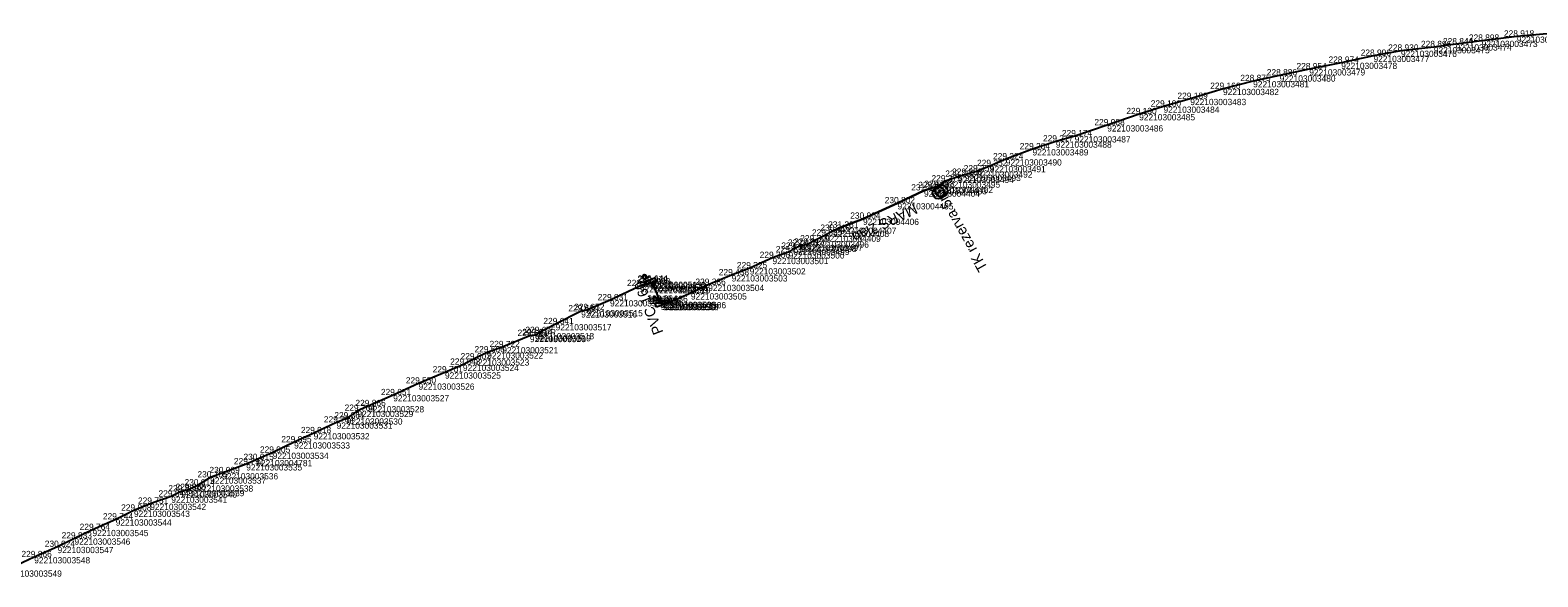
# Model space of a CAD drawing. Extents: x -771047 to -756200, y -1053876 to -1046520.
# Drawn here: x -770297.8 to -770008.9, y -1050222.5 to -1050117.8 of the extents above; entities that cross this region are included whole.
import ezdxf

# ---------------------------------------------------------------- set-up
doc = ezdxf.new("R2010")
doc.units = 0
for name, color, linetype in [('Vrstva 32', 7, 'Continuous'), ('Vrstva 33', 7, 'Continuous'), ('Vrstva 60', 7, 'Continuous'), ('Vrstva 61', 7, 'Continuous')]:
    doc.layers.add(name, color=color, linetype=linetype)

msp = doc.modelspace()

# ---------------------------------------------------------------- linework, layer by layer
at = {"layer": 'Vrstva 32'}
for points in [[(-770006.4, -1050118.41), (-770012.92, -1050119.01), (-770019.65, -1050119.81), (-770024.62, -1050120.5), (-770028.82, -1050121.03), (-770035.11, -1050121.72), (-770040.38, -1050122.7), (-770046.55, -1050124.03), (-770052.68, -1050125.27), (-770058.36, -1050126.45), (-770063.44, -1050127.54), (-770069.21, -1050129.03), (-770075.48, -1050130.95), (-770080.61, -1050132.42), (-770085.28, -1050133.87), (-770091.39, -1050136), (-770097.63, -1050138.1), (-770101.25, -1050139.11), (-770105.71, -1050140.59), (-770110.82, -1050142.52), (-770113.89, -1050143.81), (-770116.43, -1050144.83), (-770118.67, -1050145.49), (-770119.98, -1050145.87), (-770122.62, -1050146.76), (-770124, -1050147.81), (-770125.15, -1050148.04), (-770126.5, -1050148.49), (-770131.58, -1050150.93), (-770138.18, -1050153.9), (-770142.51, -1050155.61), (-770143.91, -1050156.22), (-770145.5, -1050157.13), (-770147.77, -1050158.25), (-770148.95, -1050158.89), (-770150.13, -1050159.07), (-770151.49, -1050159.65), (-770152.44, -1050160.33), (-770155.53, -1050161.41), (-770159.89, -1050163.39), (-770163.36, -1050164.73), (-770167.85, -1050166.57), (-770171.16, -1050168.19), (-770175.13, -1050169.86), (-770176.29, -1050170.25)], [(-770178.93, -1050166.17), (-770180.95, -1050166.81), (-770186.66, -1050169.51), (-770191.08, -1050171.4), (-770192.19, -1050171.63), (-770197.08, -1050174.1), (-770200.42, -1050175.8), (-770201.02, -1050176.2), (-770202.01, -1050176.35), (-770207.3, -1050178.5), (-770210.18, -1050179.5), (-770212.84, -1050180.83), (-770214.84, -1050181.87), (-770218.28, -1050183.34), (-770223.34, -1050185.46), (-770228.2, -1050187.7), (-770232.99, -1050189.8), (-770235.06, -1050190.7), (-770237.12, -1050192.15), (-770239.04, -1050192.93), (-770243.44, -1050194.98), (-770247.19, -1050196.73), (-770251.28, -1050198.71), (-770254.43, -1050200.12), (-770256.36, -1050200.93), (-770260.96, -1050202.64), (-770263.26, -1050203.46), (-770265.73, -1050204.99), (-770267.43, -1050205.86), (-770268.84, -1050206.15), (-770270.72, -1050207.12), (-770274.75, -1050208.5), (-770277.87, -1050209.82), (-770281.37, -1050211.5), (-770285.82, -1050213.51), (-770289.28, -1050215.15), (-770292.51, -1050216.76), (-770296.98, -1050218.73), (-770302.4, -1050221.28)], [(-770176.29, -1050170.25), (-770176.65, -1050170.22), (-770177.07, -1050169.78), (-770178.13, -1050167), (-770178.47, -1050166.46), (-770178.93, -1050166.17)]]:
    msp.add_lwpolyline(points, dxfattribs=at)
for centre in [(-770123.69, -1050148.94), (-770123.14, -1050148.6)]:
    msp.add_circle(centre, 1.17, dxfattribs=at)
at = {"layer": 'Vrstva 33'}
for points in [[(-770143.91, -1050156.22), (-770142.51, -1050155.61), (-770138.18, -1050153.9), (-770131.58, -1050150.93), (-770126.5, -1050148.49), (-770125.15, -1050148.04)], [(-770180.37, -1050164.99), (-770180.37, -1050164.83), (-770180.22, -1050164.65), (-770180.12, -1050164.61), (-770179.89, -1050164.64), (-770179.79, -1050164.77)], [(-770180.18, -1050165.48), (-770180.37, -1050164.99)], [(-770179.01, -1050165.03), (-770180.18, -1050165.48)], [(-770179.79, -1050164.77), (-770179.6, -1050165.26)], [(-770176.29, -1050170.25), (-770176.65, -1050170.22), (-770177.07, -1050169.78), (-770178.13, -1050167), (-770178.47, -1050166.46), (-770178.93, -1050166.17)], [(-770178.41, -1050169.2), (-770178.42, -1050169.03), (-770178.27, -1050168.85), (-770178.17, -1050168.82), (-770177.93, -1050168.84), (-770177.83, -1050168.98)], [(-770178.23, -1050169.68), (-770178.41, -1050169.2)], [(-770177.05, -1050169.24), (-770178.23, -1050169.68)], [(-770177.83, -1050168.98), (-770177.65, -1050169.46)]]:
    msp.add_lwpolyline(points, dxfattribs=at)
for points in [[(-770179.72, -1050166.66), (-770179.99, -1050165.97), (-770178.11, -1050165.25), (-770177.84, -1050165.95)], [(-770177.77, -1050170.87), (-770178.04, -1050170.17), (-770176.15, -1050169.45), (-770175.89, -1050170.15)]]:
    msp.add_lwpolyline(points, close=True, dxfattribs=at)
at = {"layer": 'Vrstva 60'}
for p, q in [((-770012.92, -1050119.01), (-770012.92, -1050119.01)), ((-770035.11, -1050121.72), (-770035.11, -1050121.72)), ((-770028.82, -1050121.03), (-770028.82, -1050121.03)), ((-770024.62, -1050120.5), (-770024.62, -1050120.5)), ((-770019.65, -1050119.81), (-770019.65, -1050119.81)), ((-770052.68, -1050125.27), (-770052.68, -1050125.27)), ((-770046.55, -1050124.03), (-770046.55, -1050124.03)), ((-770040.38, -1050122.7), (-770040.38, -1050122.7)), ((-770063.44, -1050127.54), (-770063.44, -1050127.54)), ((-770058.36, -1050126.45), (-770058.36, -1050126.45)), ((-770075.48, -1050130.95), (-770075.48, -1050130.95)), ((-770069.21, -1050129.03), (-770069.21, -1050129.03)), ((-770085.28, -1050133.87), (-770085.28, -1050133.87)), ((-770080.61, -1050132.42), (-770080.61, -1050132.42)), ((-770091.39, -1050136), (-770091.39, -1050136)), ((-770101.25, -1050139.11), (-770101.25, -1050139.11)), ((-770097.63, -1050138.1), (-770097.63, -1050138.1)), ((-770110.82, -1050142.52), (-770110.82, -1050142.52)), ((-770105.71, -1050140.59), (-770105.71, -1050140.59)), ((-770118.67, -1050145.49), (-770118.67, -1050145.49)), ((-770116.43, -1050144.83), (-770116.43, -1050144.83)), ((-770113.89, -1050143.81), (-770113.89, -1050143.81)), ((-770126.5, -1050148.49), (-770126.5, -1050148.49)), ((-770125.15, -1050148.04), (-770125.15, -1050148.04)), ((-770124, -1050147.81), (-770124, -1050147.81)), ((-770122.62, -1050146.76), (-770122.62, -1050146.76)), ((-770119.98, -1050145.87), (-770119.98, -1050145.87)), ((-770131.58, -1050150.93), (-770131.58, -1050150.93)), ((-770138.18, -1050153.9), (-770138.18, -1050153.9)), ((-770145.5, -1050157.13), (-770145.5, -1050157.13)), ((-770143.91, -1050156.22), (-770143.91, -1050156.22)), ((-770142.51, -1050155.61), (-770142.51, -1050155.61)), ((-770151.49, -1050159.65), (-770151.49, -1050159.65)), ((-770150.13, -1050159.07), (-770150.13, -1050159.07)), ((-770148.95, -1050158.89), (-770148.95, -1050158.89)), ((-770147.77, -1050158.25), (-770147.77, -1050158.25)), ((-770155.53, -1050161.41), (-770155.53, -1050161.41)), ((-770152.44, -1050160.33), (-770152.44, -1050160.33)), ((-770178.92, -1050165.96), (-770178.92, -1050165.96)), ((-770163.36, -1050164.73), (-770163.36, -1050164.73)), ((-770159.89, -1050163.39), (-770159.89, -1050163.39)), ((-770180.95, -1050166.81), (-770180.95, -1050166.81)), ((-770178.93, -1050166.17), (-770178.93, -1050166.17)), ((-770178.47, -1050166.46), (-770178.47, -1050166.46)), ((-770178.13, -1050167), (-770178.13, -1050167)), ((-770171.16, -1050168.19), (-770171.16, -1050168.19)), ((-770167.85, -1050166.57), (-770167.85, -1050166.57)), ((-770192.19, -1050171.63), (-770192.19, -1050171.63)), ((-770191.08, -1050171.4), (-770191.08, -1050171.4)), ((-770186.66, -1050169.51), (-770186.66, -1050169.51)), ((-770177.07, -1050169.78), (-770177.07, -1050169.78)), ((-770176.96, -1050170.16), (-770176.96, -1050170.16)), ((-770176.65, -1050170.22), (-770176.65, -1050170.22)), ((-770176.29, -1050170.25), (-770176.29, -1050170.25)), ((-770175.13, -1050169.86), (-770175.13, -1050169.86)), ((-770197.08, -1050174.1), (-770197.08, -1050174.1)), ((-770202.01, -1050176.35), (-770202.01, -1050176.35)), ((-770201.02, -1050176.2), (-770201.02, -1050176.2)), ((-770200.42, -1050175.8), (-770200.42, -1050175.8)), ((-770210.18, -1050179.5), (-770210.18, -1050179.5)), ((-770207.3, -1050178.5), (-770207.3, -1050178.5)), ((-770214.84, -1050181.87), (-770214.84, -1050181.87)), ((-770212.84, -1050180.83), (-770212.84, -1050180.83)), ((-770223.34, -1050185.46), (-770223.34, -1050185.46)), ((-770218.28, -1050183.34), (-770218.28, -1050183.34)), ((-770228.2, -1050187.7), (-770228.2, -1050187.7)), ((-770235.06, -1050190.7), (-770235.06, -1050190.7)), ((-770232.99, -1050189.8), (-770232.99, -1050189.8)), ((-770239.04, -1050192.93), (-770239.04, -1050192.93)), ((-770237.12, -1050192.15), (-770237.12, -1050192.15)), ((-770247.19, -1050196.73), (-770247.19, -1050196.73)), ((-770243.44, -1050194.98), (-770243.44, -1050194.98)), ((-770254.43, -1050200.12), (-770254.43, -1050200.12)), ((-770251.28, -1050198.71), (-770251.28, -1050198.71)), ((-770263.26, -1050203.46), (-770263.26, -1050203.46)), ((-770260.96, -1050202.64), (-770260.96, -1050202.64)), ((-770256.36, -1050200.93), (-770256.36, -1050200.93)), ((-770268.84, -1050206.15), (-770268.84, -1050206.15)), ((-770267.43, -1050205.86), (-770267.43, -1050205.86)), ((-770265.73, -1050204.99), (-770265.73, -1050204.99)), ((-770274.75, -1050208.5), (-770274.75, -1050208.5)), ((-770270.72, -1050207.12), (-770270.72, -1050207.12)), ((-770281.37, -1050211.5), (-770281.37, -1050211.5)), ((-770277.87, -1050209.82), (-770277.87, -1050209.82)), ((-770285.82, -1050213.51), (-770285.82, -1050213.51)), ((-770292.51, -1050216.76), (-770292.51, -1050216.76)), ((-770289.28, -1050215.15), (-770289.28, -1050215.15)), ((-770296.98, -1050218.73), (-770296.98, -1050218.73))]:
    msp.add_line(p, q, dxfattribs=at)

# ---------------------------------------------------------------- texts
at = {"layer": 'Vrstva 32'}
msp.add_text('TK rezerva 5m', height=2, rotation=119.2441, dxfattribs=at).set_placement((-770114.24, -1050163.36))
at = {"layer": 'Vrstva 33'}
for s, rotation, p in [('MARS žlab', 205.6293, (-770128.4, -1050150.95)), ('PVC 160', 110.8407, (-770176.42, -1050175.65))]:
    msp.add_text(s, height=2, rotation=rotation, dxfattribs=at).set_placement(p)
at = {"layer": 'Vrstva 60'}
for s, p in [('922103003472', (-770012.92, -1050120.21)), ('922103003476', (-770035.11, -1050122.92)), ('922103003475', (-770028.82, -1050122.23)), ('922103003474', (-770024.62, -1050121.7)), ('922103003473', (-770019.65, -1050121.02)), ('922103003479', (-770052.68, -1050126.47)), ('922103003478', (-770046.55, -1050125.23)), ('922103003477', (-770040.38, -1050123.9)), ('922103003481', (-770063.44, -1050128.74)), ('922103003480', (-770058.36, -1050127.65)), ('922103003483', (-770075.48, -1050132.15)), ('922103003482', (-770069.21, -1050130.23)), ('922103003485', (-770085.28, -1050135.07)), ('922103003484', (-770080.61, -1050133.62)), ('922103003486', (-770091.39, -1050137.2)), ('922103003488', (-770101.25, -1050140.31)), ('922103003487', (-770097.63, -1050139.3)), ('922103003490', (-770110.82, -1050143.72)), ('922103003489', (-770105.71, -1050141.79)), ('922103003493', (-770118.67, -1050146.69)), ('922103003492', (-770116.43, -1050146.03)), ('922103003491', (-770113.89, -1050145.01)), ('922103004404', (-770126.5, -1050149.69)), ('922103004403', (-770125.15, -1050149.24)), ('922103004402', (-770124, -1050149.01)), ('922103003495', (-770122.62, -1050147.96)), ('922103003494', (-770119.98, -1050147.07)), ('922103004405', (-770131.58, -1050152.13)), ('922103004406', (-770138.18, -1050155.1)), ('922103004409', (-770145.5, -1050158.33)), ('922103004408', (-770143.91, -1050157.42)), ('922103004407', (-770142.51, -1050156.81)), ('922103003499', (-770151.49, -1050160.85)), ('922103003498', (-770150.13, -1050160.27)), ('922103003497', (-770148.95, -1050160.09)), ('922103003496', (-770147.77, -1050159.45)), ('922103003501', (-770155.53, -1050162.61)), ('922103003500', (-770152.44, -1050161.53)), ('922103005131', (-770178.92, -1050167.16)), ('922103003503', (-770163.36, -1050165.93)), ('922103003502', (-770159.89, -1050164.59)), ('922103003513', (-770180.95, -1050168.02)), ('922103003512', (-770178.93, -1050167.37)), ('922103003511', (-770178.47, -1050167.66)), ('922103003510', (-770178.13, -1050168.2)), ('922103003505', (-770171.16, -1050169.39)), ('922103003504', (-770167.85, -1050167.77)), ('922103003516', (-770192.19, -1050172.83)), ('922103003515', (-770191.08, -1050172.6)), ('922103003514', (-770186.66, -1050170.71)), ('922103003509', (-770177.07, -1050170.98)), ('922103005130', (-770176.96, -1050171.36)), ('922103003508', (-770176.65, -1050171.42)), ('922103003507', (-770176.29, -1050171.45)), ('922103003506', (-770175.13, -1050171.06)), ('922103003517', (-770197.08, -1050175.3)), ('922103003520', (-770202.01, -1050177.55)), ('922103003519', (-770201.02, -1050177.4)), ('922103003518', (-770200.42, -1050177)), ('922103003522', (-770210.18, -1050180.7)), ('922103003521', (-770207.3, -1050179.7)), ('922103003524', (-770214.84, -1050183.07)), ('922103003523', (-770212.84, -1050182.03)), ('922103003526', (-770223.34, -1050186.66)), ('922103003525', (-770218.28, -1050184.54)), ('922103003527', (-770228.2, -1050188.9)), ('922103003529', (-770235.06, -1050191.9)), ('922103003528', (-770232.99, -1050191)), ('922103003531', (-770239.04, -1050194.13)), ('922103003530', (-770237.12, -1050193.35)), ('922103003533', (-770247.19, -1050197.93)), ('922103003532', (-770243.44, -1050196.18)), ('922103004781', (-770254.43, -1050201.32)), ('922103003534', (-770251.28, -1050199.91)), ('922103003537', (-770263.26, -1050204.66)), ('922103003536', (-770260.96, -1050203.84)), ('922103003535', (-770256.36, -1050202.13)), ('922103003540', (-770268.84, -1050207.35)), ('922103003539', (-770267.43, -1050207.06)), ('922103003538', (-770265.73, -1050206.19)), ('922103003542', (-770274.75, -1050209.7)), ('922103003541', (-770270.72, -1050208.32)), ('922103003544', (-770281.37, -1050212.7)), ('922103003543', (-770277.87, -1050211.02)), ('922103003545', (-770285.82, -1050214.71)), ('922103003547', (-770292.51, -1050217.96)), ('922103003546', (-770289.28, -1050216.35)), ('922103003548', (-770296.98, -1050219.93)), ('922103003549', (-770302.4, -1050222.48))]:
    msp.add_text(s, height=1.2, dxfattribs=at).set_placement(p)
at = {"layer": 'Vrstva 61'}
for s, p in [('228.844', (-770027.07, -1050120.5)), ('228.898', (-770022.1, -1050119.81)), ('228.918', (-770015.38, -1050119.01)), ('228.996', (-770042.83, -1050122.7)), ('228.930', (-770037.56, -1050121.72)), ('228.896', (-770031.28, -1050121.03)), ('228.886', (-770060.82, -1050126.45)), ('228.954', (-770055.13, -1050125.27)), ('228.974', (-770049, -1050124.03)), ('229.166', (-770071.66, -1050129.03)), ('228.875', (-770065.9, -1050127.54)), ('229.100', (-770083.06, -1050132.42)), ('229.189', (-770077.94, -1050130.95)), ('229.130', (-770087.73, -1050133.87)), ('229.174', (-770100.08, -1050138.1)), ('229.088', (-770093.85, -1050136)), ('229.284', (-770108.16, -1050140.59)), ('229.217', (-770103.7, -1050139.11)), ('229.352', (-770116.34, -1050143.81)), ('229.324', (-770113.27, -1050142.52)), ('229.375', (-770125.07, -1050146.76)), ('229.282', (-770122.43, -1050145.87)), ('229.238', (-770121.12, -1050145.49)), ('229.359', (-770118.89, -1050144.83)), ('231.292', (-770128.95, -1050148.49)), ('229.823', (-770127.61, -1050148.04)), ('229.498', (-770126.46, -1050147.81)), ('230.802', (-770134.03, -1050150.93)), ('231.281', (-770144.87, -1050155.61)), ('230.904', (-770140.63, -1050153.9)), ('229.300', (-770150.22, -1050158.25)), ('229.635', (-770147.96, -1050157.13)), ('230.210', (-770146.36, -1050156.22)), ('229.306', (-770157.98, -1050161.41)), ('229.230', (-770154.89, -1050160.33)), ('229.401', (-770153.84, -1050159.65)), ('229.473', (-770152.58, -1050159.07)), ('229.313', (-770151.4, -1050158.89)), ('229.325', (-770162.35, -1050163.39)), ('229.652', (-770183.4, -1050166.81)), ('230.079', (-770181.38, -1050166.17)), ('230.644', (-770181.37, -1050165.96)), ('229.988', (-770180.92, -1050166.46)), ('229.179', (-770180.58, -1050167)), ('229.386', (-770170.3, -1050166.57)), ('229.438', (-770165.82, -1050164.73)), ('229.931', (-770189.02, -1050169.51)), ('229.064', (-770179.52, -1050169.78)), ('229.636', (-770177.58, -1050169.86)), ('229.399', (-770173.62, -1050168.19)), ('229.684', (-770194.64, -1050171.63)), ('229.652', (-770193.53, -1050171.4)), ('230.646', (-770179.41, -1050170.16)), ('229.979', (-770179.1, -1050170.22)), ('229.956', (-770178.74, -1050170.25)), ('229.675', (-770202.87, -1050175.8)), ('229.641', (-770199.43, -1050174.1)), ('229.722', (-770209.75, -1050178.5)), ('229.621', (-770204.37, -1050176.35)), ('229.634', (-770203.47, -1050176.2)), ('229.602', (-770215.29, -1050180.83)), ('229.606', (-770212.63, -1050179.5)), ('229.701', (-770220.64, -1050183.34)), ('229.643', (-770217.29, -1050181.87)), ('229.550', (-770225.79, -1050185.46)), ('229.866', (-770235.44, -1050189.8)), ('229.651', (-770230.56, -1050187.7)), ('229.784', (-770241.49, -1050192.93)), ('229.861', (-770239.48, -1050192.15)), ('229.764', (-770237.51, -1050190.7)), ('229.918', (-770245.89, -1050194.98)), ('229.905', (-770253.73, -1050198.71)), ('229.895', (-770249.64, -1050196.73)), ('229.791', (-770258.72, -1050200.93)), ('230.015', (-770256.89, -1050200.12)), ('230.105', (-770265.71, -1050203.46)), ('230.089', (-770263.41, -1050202.64)), ('229.844', (-770273.17, -1050207.12)), ('229.889', (-770271.29, -1050206.15)), ('229.888', (-770269.89, -1050205.86)), ('230.014', (-770268.19, -1050204.99)), ('229.908', (-770280.33, -1050209.82)), ('229.751', (-770277.1, -1050208.5)), ('229.744', (-770283.82, -1050211.5)), ('229.833', (-770291.73, -1050215.15)), ('229.764', (-770288.27, -1050213.51)), ('229.866', (-770299.43, -1050218.73)), ('230.024', (-770294.96, -1050216.76))]:
    msp.add_text(s, height=1.2, dxfattribs=at).set_placement(p)

doc.saveas('drawing.dxf')
